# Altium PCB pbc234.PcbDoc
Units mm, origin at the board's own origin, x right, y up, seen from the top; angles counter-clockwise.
Board outline 80.01 x 87.38 mm, 2 copper layers (Top Layer, Bottom Layer); 33 components, 27 nets, 113 pads, 0 vias.
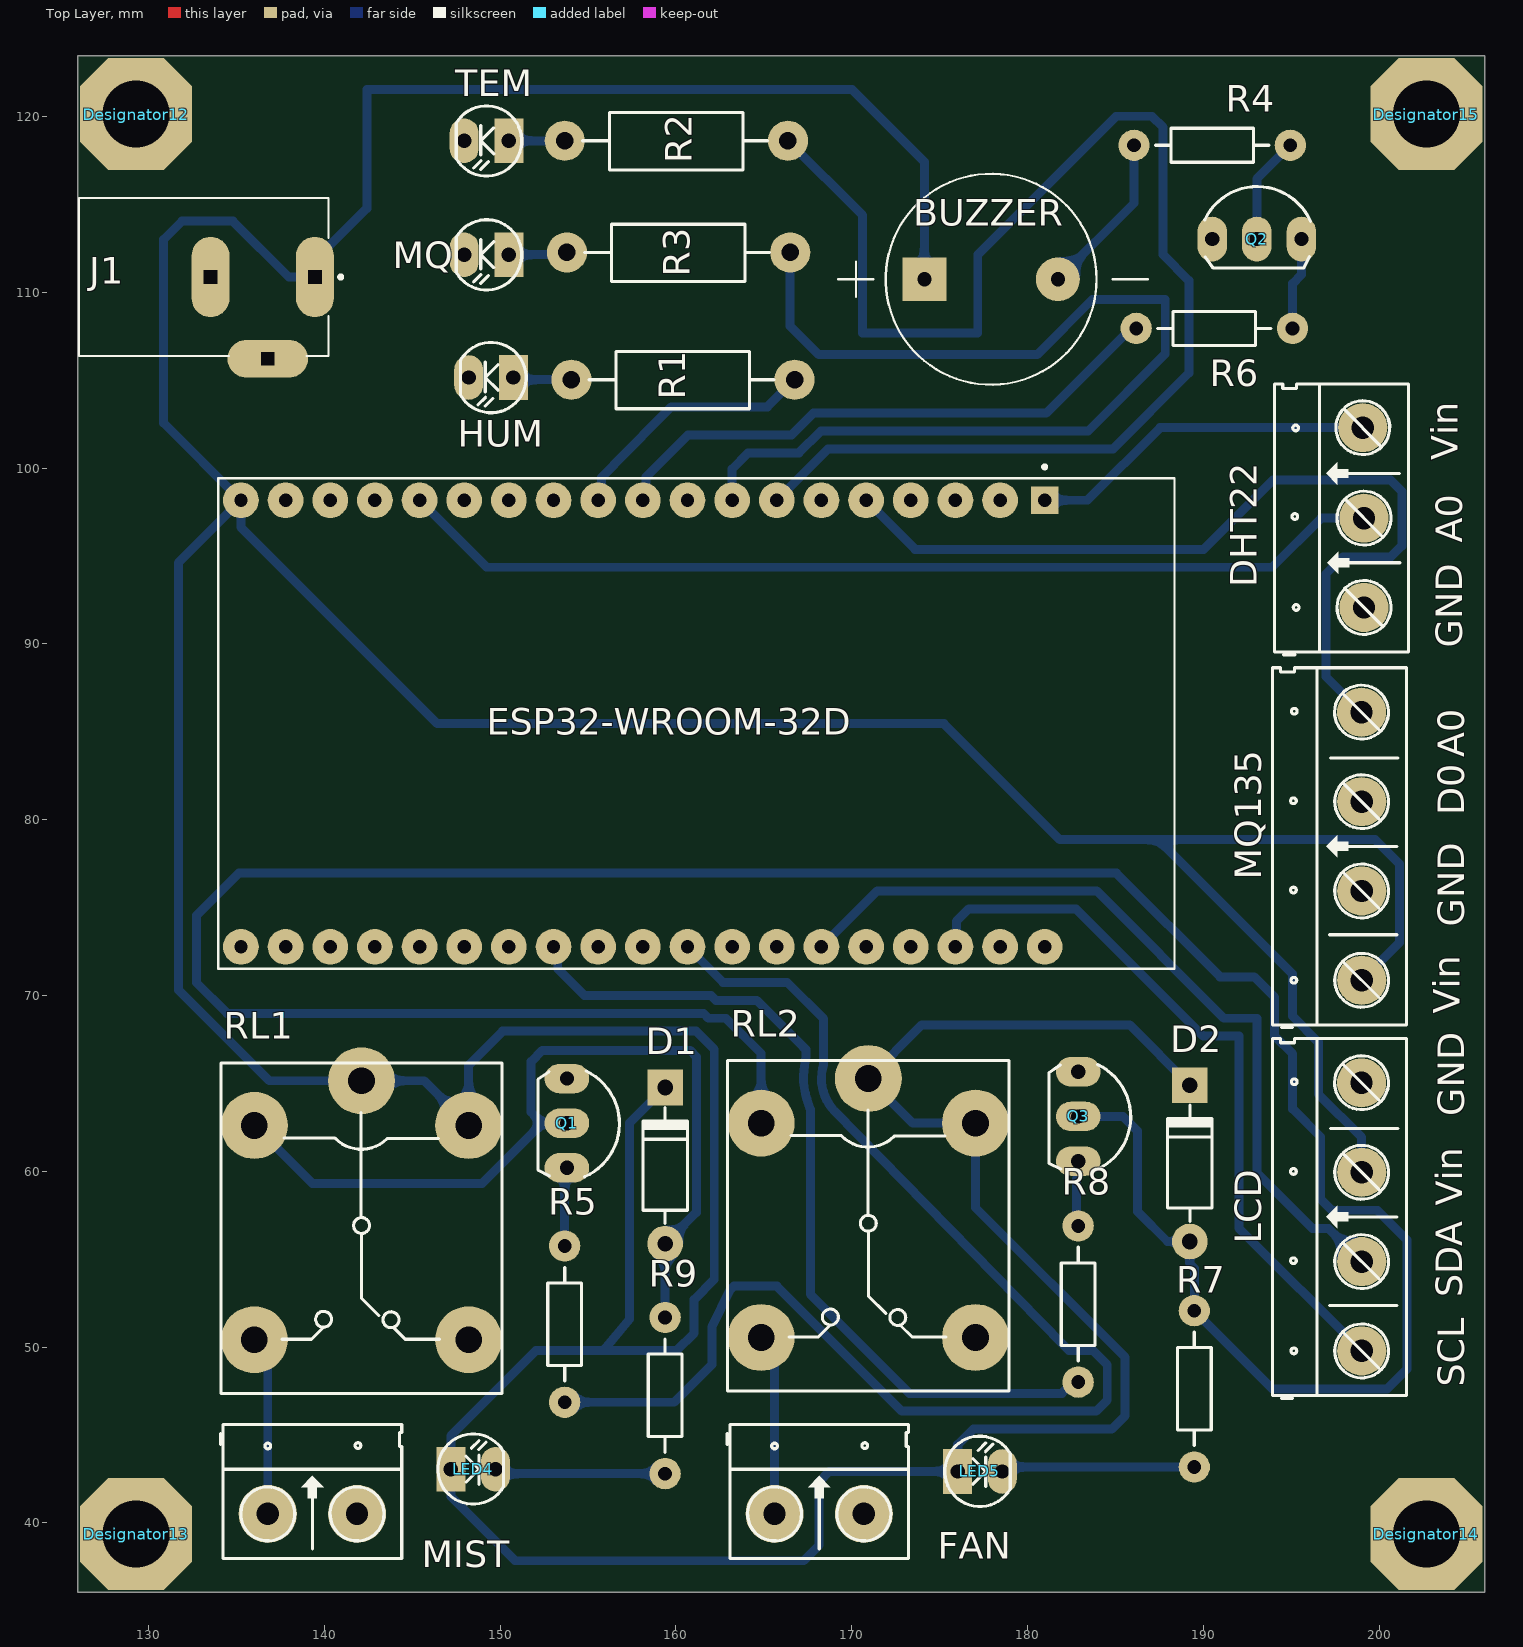
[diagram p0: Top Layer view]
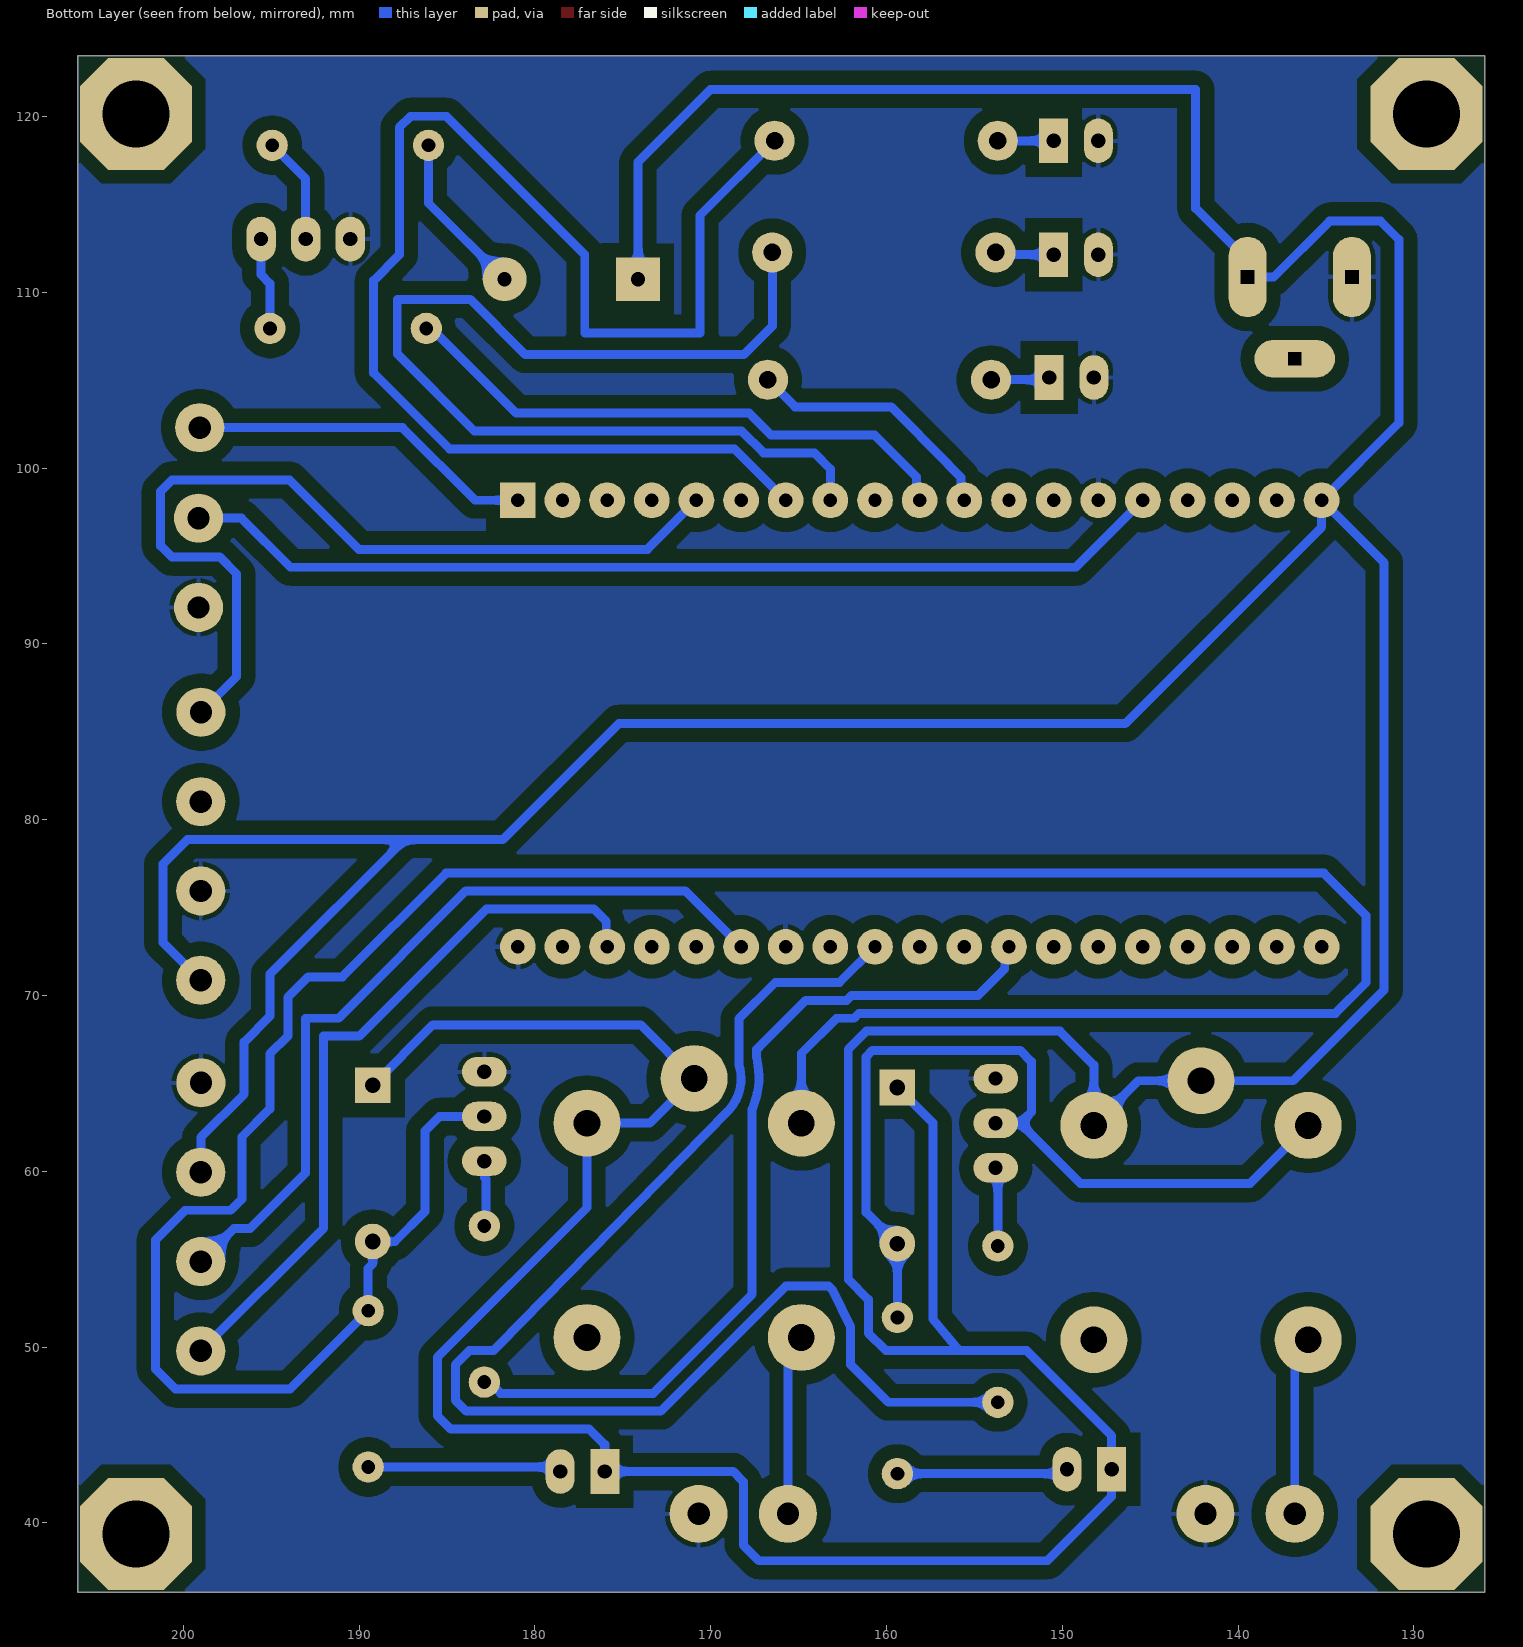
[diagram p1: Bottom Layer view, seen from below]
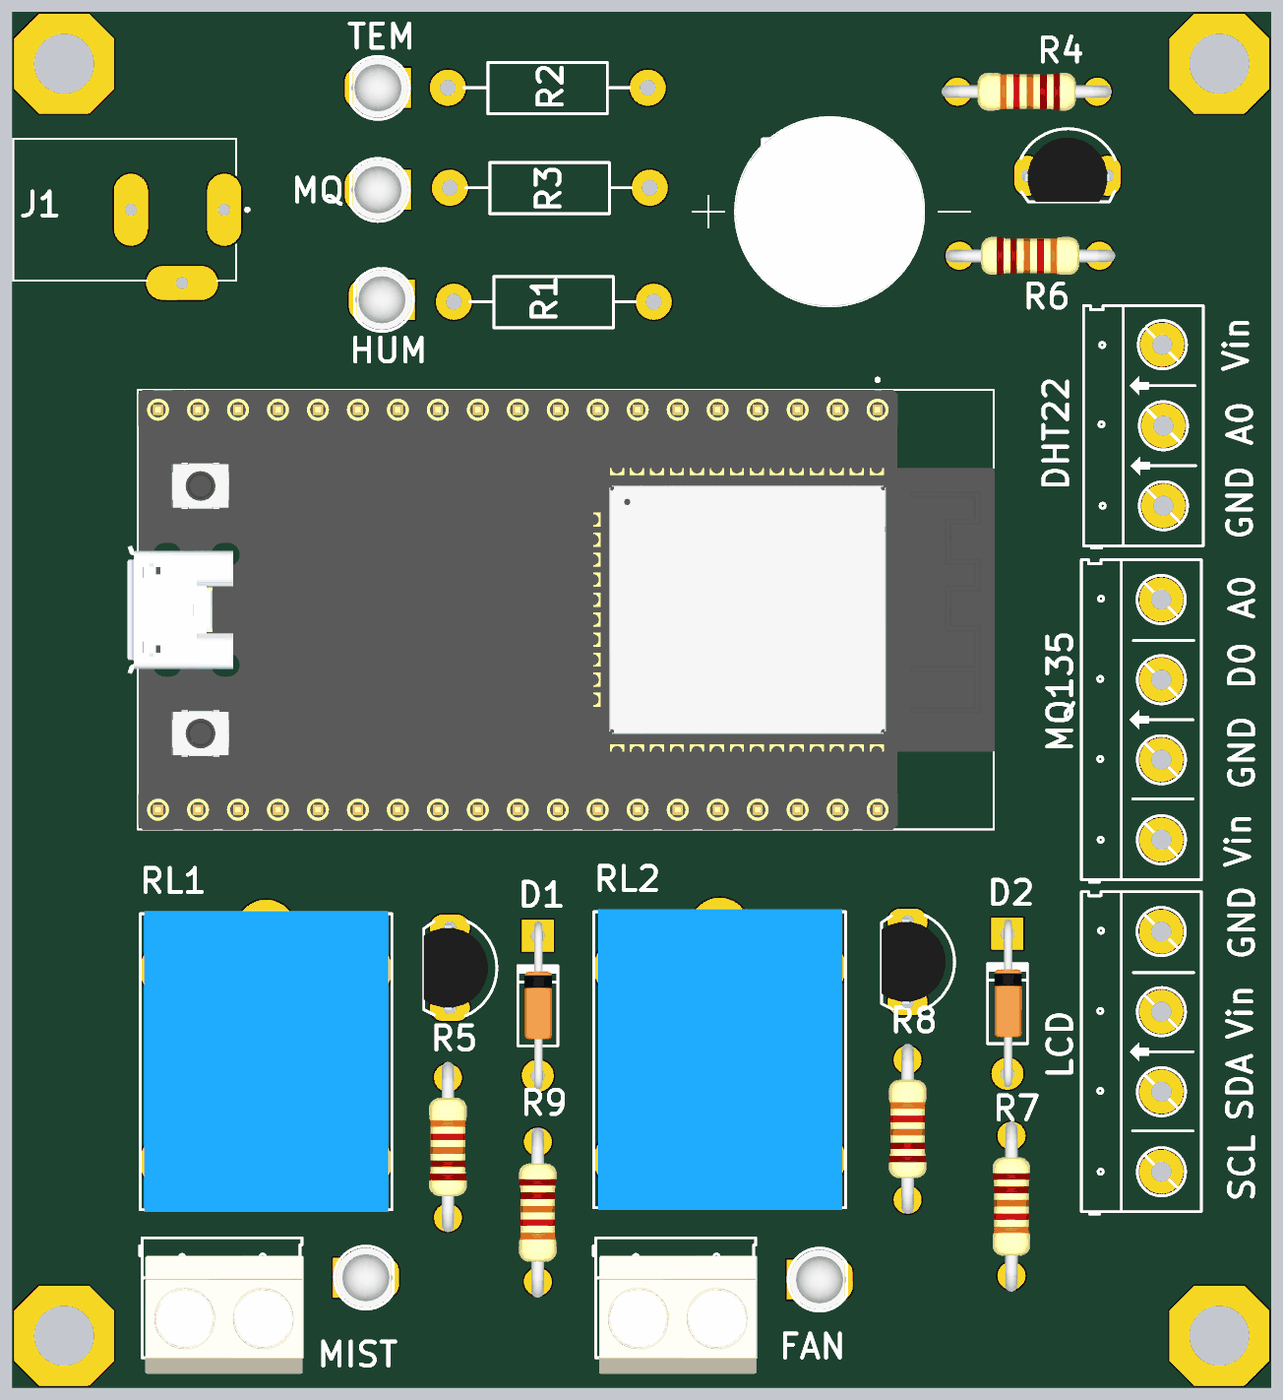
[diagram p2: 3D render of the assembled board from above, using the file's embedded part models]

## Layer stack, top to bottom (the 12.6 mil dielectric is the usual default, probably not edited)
Top Solder: solder mask 0.0102, Solder Resist, Dk 3.5
Top Layer: signal copper 0.0356
Dielectric 1: dielectric 0.32, FR-4, Dk 4.8
Bottom Layer: signal copper 0.0356
Bottom Solder: solder mask 0.0102, Solder Resist, Dk 3.5

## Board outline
125.984,36.068 125.984,123.444 205.994,123.444 205.994,36.068

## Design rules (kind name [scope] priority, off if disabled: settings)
Clearance [All] p1: gap=0.508 ignorepadtopadclearanceinfootprint=TRUE except(0.8: Arc-Fill Arc-Poly Arc-Region Track-Fill Track-Poly Track-Region SMDPad-Fill SMDPad-Poly SMDPad-Region THPad-Fill THPad-Poly THPad-Region Via-Fill Via-Poly Via-Region Fill-Fill Fill-Poly Fill-Region Poly-Poly Poly-Region Region-Region)
PolygonConnect [All] p1: connectstyle=Relief reliefconductorwidth=0.254 reliefentries=4 polygonreliefangle="90 Angle" airgapwidth=0.254
RoutingLayers [All] p1: top layer_v5=FALSE bottom layer_v5=TRUE
RoutingVias [All] p1: holewidth=0.711 width=1.27 viastyle="Through Hole" minholewidth=0.711 minwidth=1.27 maxholewidth=0.711 maxwidth=1.27
SolderMaskExpansion [All] p1: expansion=0.102 istentingtop=FALSE
Width [All] p1: maxlimit=0.635 minlimit=0.381 preferedwidth=0.508
29 further rules are at their usual default settings.

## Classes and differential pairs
component class machnguyenly: BUZZER D1 D2 DHT22 ESP32-WROOM-32D FAN HUM J1 LCD LED4 LED5 MIST MQ MQ135 Q1 Q2 Q3 R1 R2 R3 R4 R5 R6 R7 R8 R9 RL1 RL2 TEM

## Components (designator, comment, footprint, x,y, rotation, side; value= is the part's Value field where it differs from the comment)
BUZZER "CMI-1210-5-95T" XDCR_CMI-1210-5-95T 177.927,110.744 r0 top (schematic designator LS1)
D1 "1N4007" D1A 159.385,55.88 r270 top
D2 "1N4007" D1A 189.23,56.007 r270 top
Designator12 "Comment" VIT 129.286,120.142 r0 top
Designator13 "Comment" VIT 129.286,39.37 r0 top
Designator14 "Comment" VIT 202.692,39.37 r0 top
Designator15 "Comment" VIT 202.692,120.142 r0 top
DHT22 "DHT22" HED3 199.136,92.075 r90 top value="Header 3"
ESP32-WROOM-32D "ESP32-DEVKITC-32D" MODULE_ESP32-DEVKITC-32D 161.215,85.471 r270 top (schematic designator U2)
FAN "Header 2" HED2 165.608,40.513 r0 top
HUM "LED" LED-3 150.749,105.156 r180 top value="LED 3 ly Single Colour" (schematic designator LED1)
J1 "DC-005" MPD_EJ503B 136.779,110.871 r270 top
LCD "LCD1602 I2C" HED4 199.009,49.784 r90 top value="Header 4"
LED4 "LED" LED-3 147.193,43.053 r0 top value="LED 3 ly Single Colour"
LED5 "LED" LED-3 176.022,42.926 r0 top value="LED 3 ly Single Colour"
MIST "Header 2" HED2 136.779,40.513 r0 top
MQ "LED" LED-3 150.495,112.141 r180 top value="LED 3 ly Single Colour" (schematic designator LED3)
MQ135 "MQ135" HED4 199.009,70.866 r90 top value="Header 4"
Q1 "C1815" QTO-92 153.797,62.738 r270 top
Q2 "C1815" QTO-92 193.04,113.03 r0 top
Q3 "C1815" QTO-92 182.88,63.119 r270 top
R1 "220" R1W 166.751,105.029 r180 top value="R1W - 100"
R2 "220" R1W 166.37,118.618 r180 top value="R1W - 100"
R3 "220" R1W 166.497,112.268 r180 top value="R1W - 100"
R4 "Res1" R1/4W 186.055,118.364 r0 top value=1K
R5 "Res1" R1/4W 153.67,55.753 r270 top value=1K
R6 "Res1" R1/4W 195.072,107.95 r180 top value=1K
R7 "Res1" R1/4W 189.484,43.18 r90 top value=1K
R8 "Res1" R1/4W 182.88,56.896 r270 top value=1K
R9 "Res1" R1/4W 159.385,42.799 r90 top value=1K
RL1 "Relay 5V" RL_SPDT_10A 142.113,65.151 r270 top value="Relay SPDT, 10A, 12V"
RL2 "Relay 5V" RL_SPDT_10A 170.942,65.278 r270 top value="Relay SPDT, 10A, 12V"
TEM "LED" LED-3 150.495,118.618 r180 top value="LED 3 ly Single Colour" (schematic designator LED2)

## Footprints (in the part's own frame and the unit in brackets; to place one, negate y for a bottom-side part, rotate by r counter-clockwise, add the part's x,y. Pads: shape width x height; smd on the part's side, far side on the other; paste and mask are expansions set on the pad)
D1A [mil] "Diode 1A, W 100mil, L 350mil"
  round 80 hole 35: 1(0,0)
  rect 80x80 hole 35: 2(-350,0)
  silkscreen extent -305,-50 -45,50, body extent -386,-33 34,36, height 84
HED2 [mil] "Header 2, 2 pin, hight 300mil, Pin to Pin 200, Colour Green"
  round 130 hole 50: 1(0,0) 2(200,0)
  silkscreen extent -106,-100 300,200, body extent -92,-140 302,155, height 394
HED3 [mil] "Header 3, 3 pin, hight 300mil, Pin to Pin 200, Colour Green"
  round 110 hole 50: 1(0,0) 2(200,0) 3(402.62,2.62)
  silkscreen extent -106,-100 500,200
HED4 [mil] "Header 4, 4 pin, hight 300mil, Pin to Pin 200, Colour Green"
  round 110 hole 50: 1(0,0) 2(200,0) 3(400.06,0.06) 4(600.39,0.39)
  silkscreen extent -106,-100 700,200
LED-3 [mil] "LED 2 PIN, 3ly Only colour"
  rect 65x100 hole 32: 1(0,0)
  oval 65x100 hole 32: 2(100,0)
  silkscreen extent -29,-78 118,79, body extent -25,-75 113,75, height 217
MODULE_ESP32-DEVKITC-32D [mil]
  rect 61.42x61.42 / inner round 61.42 / far side rect 80x80 hole 30: J2-1(-500,777.95)
  round 80 hole 30: J2-2(-500,677.95) J2-3(-500,577.95) J2-4(-500,477.95) J2-5(-500,377.95) J2-6(-500,277.95) J2-7(-500,177.95) J2-8(-500,77.95) J2-9(-500,-22.05) J2-10(-500,-122.05) J2-11(-500,-222.05) J2-12(-500,-322.05) J2-13(-500,-422.05) J2-14(-500,-522.05) J2-15(-500,-622.05) J2-16(-500,-722.05) J2-17(-500,-822.05) J2-18(-500,-922.05) J2-19(-500,-1022.05) J3-1(500,777.95) J3-2(500,677.95) J3-3(500,577.95) J3-4(500,477.95) J3-5(500,377.95) J3-6(500,277.95) J3-7(500,177.95) J3-8(500,77.95) J3-9(500,-22.05) J3-10(500,-122.05) J3-11(500,-222.05) J3-12(500,-322.05) J3-13(500,-422.05) J3-14(500,-522.05) J3-15(500,-622.05) J3-16(500,-722.05) J3-17(500,-822.05) J3-18(500,-922.05) J3-19(500,-1022.05)
  silkscreen extent -579,-1073 549,1069, body extent -550,-1098 550,1071, height 263
MPD_EJ503B [mil]
  oval 180x85 hole 29.92 square: 1(0,105.51) 2(0,-127.95)
  oval 85x180 hole 29.92 square: 3(183.07,0)
  silkscreen extent -177,-423 177,167
QTO-92 [mil] "TO-92"
  oval 66x100 hole 32: 1(-100,0) 2(0,0) 3(100,0)
  silkscreen extent -117,-65 120,118, body extent -109,-66 109,95, height 245
R1/4W [mil] "R 1/4W, 2 Pin, 350mil"
  round 70 hole 31: 1(0,0) 2(350,0)
  silkscreen extent 48,-38 302,38, body extent -40,-47 386,47, height 111
R1W [mil] "R 1W, 2 pin, 500mil"
  round 90 hole 39.37: 1(0,0) 2(500,0)
  silkscreen extent 46,-63 460,65
RL_SPDT_10A [mil] "Relay SPDT, 5 pin, 10A,W 650mil, L 800mil, H 800mil"
  round 150 hole 60: 1(0,0) 2(580,240) 3(580,-240) 4(100,-240) 5(100,240)
  silkscreen extent -40,-315 700,315, body extent -46,-304 706,306, height 602
VIT [mm] "VIT"
  oct 6.35x6.35 hole 3.81: VIT1(0,0)
XDCR_CMI-1210-5-95T [mm]
  round 2.5 hole 0.8: N(3.8,0)
  rect 2.5x2.5 / inner round 2.5 / far side rect 2.5x2.5 hole 0.8: P(-3.8,0)
  silkscreen extent -8.69,-6 8.92,6, body extent -6,-6 6,6, height 7

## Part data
BUZZER: "12 mm, 5 Vdc, 98 dB, Through Hole, Magnetic Audio Indicator Buzzer", Package=None
D1 D2: library part D1A, "Diode 1A"
DHT22: library part Hed3, "Header 3 (Green)"
ESP32-WROOM-32D: "WiFi Development Tools (802.11) ESP32 General Development Kit, ESP32-WROOM-32D on the board", Package=None
FAN MIST: library part Hed2, "Header 2 (Green)"
HUM LED4 LED5 MQ TEM: "LED Single colour Green and Red"
J1: library part EJ503B, "CONN PWR JACK 2.5X5.5MM SOLDER", Package=None
LCD MQ135: library part Hed4, "Header 4 (Green)"
Q1 Q2 Q3: "NPN 600mW, ECB"
R1 R2 R3: library part R1W, "Resistor 1W"
R4 R5 R6 R7 R8 R9: library part Res1_4, "Resistor", Manufacturer="Generic Components"
RL1 RL2: library part "Relay 1", "Relay SPDT,10A - 12VDC 5 Pin"

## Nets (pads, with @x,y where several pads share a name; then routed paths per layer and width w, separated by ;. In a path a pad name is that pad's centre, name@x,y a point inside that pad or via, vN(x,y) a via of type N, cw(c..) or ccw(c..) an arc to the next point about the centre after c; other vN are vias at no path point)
3.3V: DHT22.3 ESP32-WROOM-32D.J2-1 | length 19.8
  Bottom Layer w0.508: ESP32-WROOM-32D.J2-1 183.405,98.171 187.535,102.302 DHT22.3
+5: BUZZER.P D1.2 D2.2 ESP32-WROOM-32D.J2-19 J1.1 LCD.3 LED4.1 LED5.1 MQ135.1 RL1.1 RL1.5 RL2.1 RL2.5 | length 400.5
  Bottom Layer w0.508: D1.2 157.353,62.738 157.353,51.587 155.88,49.809 ; BUZZER.P 174.127,117.414 170.002,121.539 142.418,121.539 142.418,114.78 139.459,111.821 J1.1 137.973,110.871 134.798,114.046 131.902,114.046 130.861,113.005 130.861,102.565 ESP32-WROOM-32D.J2-19 ; D2.2 185.801,68.326 173.99,68.326 RL2.1 173.482,62.738 RL2.5 177.038,57.926 185.547,49.417 185.547,46.101 184.785,45.339 176.911,45.339 176.022,44.45 LED5.1 168.732,42.926 168.148,42.342 168.148,38.735 167.259,37.846 150.851,37.846 147.193,41.504 LED4.1 147.193,44.958 152.044,49.809 155.88,49.809 ; LCD.3 199.007,61.924 196.545,64.387 196.545,67.345 195.072,68.819 195.072,71.216 187.421,78.867 ; MQ135.1 201.168,73.025 201.168,77.47 199.771,78.867 187.421,78.867 ; ESP32-WROOM-32D.J2-19 135.255,96.647 146.431,85.471 175.235,85.471 181.839,78.867 187.421,78.867 ; ESP32-WROOM-32D.J2-19 131.699,94.615 131.699,70.318 136.866,65.151 RL1.1 145.669,65.151 RL1.5 148.209,66.04 150.139,67.97 161.145,67.97 162.179,66.936 162.179,53.848 161.036,52.705 161.036,50.8 160.045,49.809 155.88,49.809
B26: ESP32-WROOM-32D.J2-10 R6.2 | length 32.8
  Bottom Layer w0.508: ESP32-WROOM-32D.J2-10 158.293,98.349 158.293,99.492 160.68,101.879 166.57,101.879 167.814,103.124 181.059,103.124 185.885,107.95 R6.2
DHT-13: DHT22.2 ESP32-WROOM-32D.J2-15 | length 56.5
  Bottom Layer w0.508: ESP32-WROOM-32D.J2-15 149.225,94.361 193.904,94.361 196.698,97.155 DHT22.2
G21: ESP32-WROOM-32D.J3-6 LCD.2 | length 45.9
  Bottom Layer w0.508: ESP32-WROOM-32D.J3-6 171.45,75.946 183.923,75.946 191.162,68.707 193.04,68.707 193.04,59.914 196.215,56.739 197.134,56.739 LCD.2
G22: ESP32-WROOM-32D.J3-3 LCD.1 | length 41.6
  Bottom Layer w0.508: ESP32-WROOM-32D.J3-3 175.946,72.822 175.946,74.219 176.657,74.93 182.753,74.93 189.992,67.691 192.024,67.691 192.024,56.769 LCD.1
GND: DHT22.1 ESP32-WROOM-32D.J2-14 ESP32-WROOM-32D.J3-1 ESP32-WROOM-32D.J3-7 FAN.2 HUM.2 J1.2 LCD.4 MIST.2 MQ135.2 MQ.2 Q1.1 Q2.1 Q3.1 TEM.2
H-27: ESP32-WROOM-32D.J2-11 R1.1 | length 14.7
  Bottom Layer w0.508: ESP32-WROOM-32D.J2-11 155.773,98.369 155.773,99.472 156.464,100.163 156.464,100.203 159.741,103.48 165.202,103.48 R1.1
MQ-33: ESP32-WROOM-32D.J2-8 R3.1 | length 59.7
  Bottom Layer w0.508: ESP32-WROOM-32D.J2-8 163.195,99.949 164.109,100.863 166.991,100.863 168.235,102.108 183.439,102.108 187.833,106.502 187.833,109.601 183.693,109.601 180.543,106.451 168.123,106.451 166.497,108.077 R3.1
MQ-34: ESP32-WROOM-32D.J2-5 MQ135.4 | length 50.3
  Bottom Layer w0.508: ESP32-WROOM-32D.J2-5 173.609,95.377 190.017,95.377 193.954,99.314 200.66,99.314 201.295,98.679 201.295,95.58 200.66,94.945 197.942,94.945 196.977,93.98 196.977,88.138 MQ135.4
NetD1_1: D1.1 Q1.2 R9.2 RL1.4 | length 49.7
  Bottom Layer w0.508: RL1.4 139.319,59.309 148.971,59.309 151.003,61.341 152.4,62.738 ; Q1.2 152.4,62.738 ; R9.2 D1.1 161.163,57.658 161.163,66.516 160.8,66.878 152.4,66.878 151.765,66.243 151.765,63.373 152.4,62.738
NetD2_1: D2.1 Q3.2 R7.2 RL2.4 | length 163
  Bottom Layer w0.508: RL2.4 164.846,66.7 162.839,68.707 161.845,68.707 161.566,68.986 134.468,68.986 132.715,70.739 132.715,74.549 135.128,76.962 185.05,76.962 190.948,71.064 192.882,71.064 194.056,69.889 194.056,67.694 195.072,66.678 195.072,63.551 196.672,61.951 196.672,58.42 197.307,57.785 199.898,57.785 201.574,56.109 201.574,48.743 200.457,47.625 193.929,47.625 R7.2 189.484,54.483 189.23,54.737 D2.1 187.96,56.007 186.258,57.709 186.258,62.281 185.42,63.119 Q3.2
NetFAN_1: FAN.1 RL2.3 | length 10.3
  Bottom Layer w0.508: RL2.3 164.846,49.859 165.608,49.097 FAN.1
NetLED1_1: HUM.1 R1.2 | length 3.4
  Bottom Layer w0.508: HUM.1 150.876,105.029 R1.2
NetLED2_1: R2.2 TEM.1 | length 3.2
  Bottom Layer w0.508: TEM.1 R2.2
NetLED3_1: MQ.1 R3.2 | length 3.4
  Bottom Layer w0.508: MQ.1 153.67,112.141 R3.2
NetLED4_2: LED4.2 R9.1 | length 9.9
  Bottom Layer w0.508: LED4.2 149.733,42.799 R9.1
NetLED5_2: LED5.2 R7.1 | length 11.2
  Bottom Layer w0.508: LED5.2 178.562,43.18 R7.1
NetLS1_N: BUZZER.N R4.1 | length 9.4
  Bottom Layer w0.508: BUZZER.N 186.055,115.072 R4.1
NetMIST_1: MIST.1 RL1.3 | length 10.2
  Bottom Layer w0.508: RL1.3 136.017,49.732 136.779,48.97 MIST.1
NetQ1_3: Q1.3 R5.1 | length 4.6
  Bottom Layer w0.508: R5.1 153.67,60.198 Q1.3
NetQ2_2: Q2.2 R4.2 | length 6.1
  Bottom Layer w0.508: Q2.2 193.04,116.459 R4.2
NetQ2_3: Q2.3 R6.1 | length 5.3
  Bottom Layer w0.508: R6.1 195.072,110.49 195.58,110.998 Q2.3
NetQ3_3: Q3.3 R8.1 | length 3.8
  Bottom Layer w0.508: R8.1 182.786,56.99 182.786,59.563 182.88,59.657 Q3.3
R16: ESP32-WROOM-32D.J3-12 R8.2 | length 49.2
  Bottom Layer w0.508: ESP32-WROOM-32D.J3-12 153.276,72.53 153.276,71.514 154.788,70.002 161.987,70.002 162.266,69.723 164.587,69.723 167.261,67.049 167.386,66.924 167.386,66.503 167.289,65.747 ccw(c170.942,65.278) 167.448,64.113 167.645,63.522 167.645,53.005 173.279,47.371 181.947,47.371 182.582,48.006 R8.2
R18: ESP32-WROOM-32D.J3-9 R5.2 | length 77
  Bottom Layer w0.508: R5.2 159.893,46.863 162.052,49.022 162.052,51.16 163.08,53.258 163.14,53.318 163.288,53.467 165.735,53.467 172.847,46.355 183.896,46.355 184.531,46.99 184.531,48.997 183.718,49.809 182.557,49.809 182.347,49.809 182.049,50.107 169.035,63.413 cw(c170.942,65.278) 168.402,66.091 168.402,68.667 166.33,70.739 162.687,70.739 ESP32-WROOM-32D.J3-9
T-32: ESP32-WROOM-32D.J2-7 R2.1 | length 78.8
  Bottom Layer w0.508: ESP32-WROOM-32D.J2-7 168.656,101.092 184.861,101.092 189.179,105.41 189.179,110.668 187.706,112.141 187.706,119.38 187.071,120.015 185.039,120.015 177.165,112.141 177.165,107.696 170.612,107.696 170.612,114.376 R2.1
pads on no net: Designator12.VIT1 Designator13.VIT1 Designator14.VIT1 Designator15.VIT1 ESP32-WROOM-32D.J2-2 ESP32-WROOM-32D.J2-3 ESP32-WROOM-32D.J2-4 ESP32-WROOM-32D.J2-6 ESP32-WROOM-32D.J2-9 ESP32-WROOM-32D.J2-12 ESP32-WROOM-32D.J2-13 ESP32-WROOM-32D.J2-16 ESP32-WROOM-32D.J2-17 ESP32-WROOM-32D.J2-18 ESP32-WROOM-32D.J3-2 ESP32-WROOM-32D.J3-4 ESP32-WROOM-32D.J3-5 ESP32-WROOM-32D.J3-8 ESP32-WROOM-32D.J3-10 ESP32-WROOM-32D.J3-11 ESP32-WROOM-32D.J3-13 ESP32-WROOM-32D.J3-14 ESP32-WROOM-32D.J3-15 ESP32-WROOM-32D.J3-16 ESP32-WROOM-32D.J3-17 ESP32-WROOM-32D.J3-18 ESP32-WROOM-32D.J3-19 J1.3 MQ135.3 RL1.2 RL2.2

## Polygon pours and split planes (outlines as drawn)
GND on Bottom Layer "GND_L02_P004" (solid, pour order 4): 125.984,123.444 125.984,36.068 205.994,36.068 205.994,123.444
GND on Bottom Layer "NONET_L02_P002" (solid, remove dead copper, shelved, pour order 2): 125.984,36.068 125.984,123.444 205.994,123.444 205.994,36.068

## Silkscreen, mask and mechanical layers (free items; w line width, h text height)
Top Overlay:
  text "Vin" at 204.47,100.457 h1.52 r90
  text "A0" at 204.724,95.758 h1.52 r90
  text "GND" at 204.724,89.789 h1.52 r90
  text "A0" at 204.851,83.566 h1.52 r90
  text "D0" at 204.851,80.264 h1.52 r90
  text "GND" at 204.851,73.914 h1.52 r90
  text "Vin" at 204.597,68.961 h1.52 r90
  text "GND" at 204.851,63.119 h1.52 r90
  text "Vin" at 204.724,58.039 h1.52 r90
  text "SDA" at 204.724,52.832 h1.52 r90
  text "SCL" at 204.851,47.752 h1.52 r90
